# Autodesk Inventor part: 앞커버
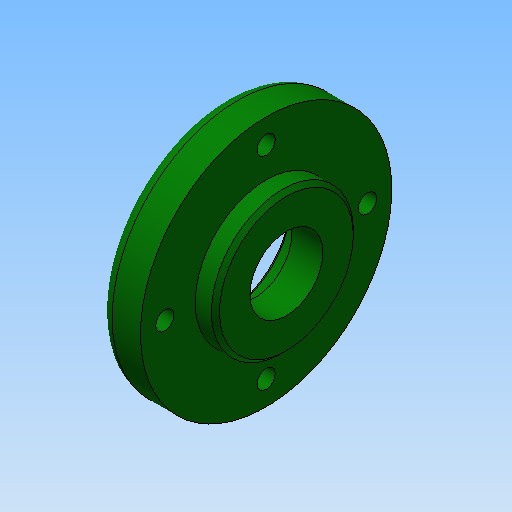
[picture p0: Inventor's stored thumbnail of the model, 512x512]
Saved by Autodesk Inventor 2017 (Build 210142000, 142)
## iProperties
Created: 2015-12
Part Number: 앞커버
Document SubType Name: Modeling
Designer: mdu
Density: 2.71 g/cm^3
Material: 알루미늄 6061
Mass: 70.9292 g
Surface Area: 93.9278 cm^2
Volume: 26.1731 cm^3
Appearance: 진녹색
Author: mdu
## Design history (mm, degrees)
sketch "스케치1"
  geometry: L1 (-7.5, 0)-(7.5, 0); L2 (-7.5, 0)-(-7.5, 31); L3 (-7.5, 31)-(2.5, 31); L4 (2.5, 31)-(2.5, 17.5); L5 (2.5, 17.5)-(7.5, 17.5); L6 (7.5, 17.5)-(7.5, 0); 2 further points
  constraints: 12 end point, 3 perpendicular, 1 coincident, 1 horizontal, 1 midpoint, 1 parallel
  dimensions: "d0" = 15 distance of L1.start L1.end; "d1" = 62 diameter of L3 L1; "d2" = 35 diameter of L5 L1; "d5" = 10 distance of L2.end L3.end
revolve "회전1" sketch "스케치1" stored, may be unused: angle "d6" = 90 deg
sketch "스케치2" dims "d42" = 50
  geometry: 3 further points
  constraints: 2 vertical alignment, 1 coincident, 2 other
hole "구멍1" sketch "스케치2" at (0, 25) diameter "d8" = 4.5; stored, may be unused: countersink angle "d12" = 90 deg, drill point angle "d14" = 118 deg; dims "d9" = 6, "d10" = 8, "d11" = 4.4, "d13" = 8
hole "구멍2" diameter "d20" = 18; stored, may be unused: countersink angle "d24" = 90 deg, drill point angle "d26" = 0 deg; dims "d18" = 10, "d19" = 10, "d21" = 6, "d22" = 8, "d23" = 4.4, "d25" = 8
hole "구멍3" diameter "d34" = 30; stored, may be unused: countersink angle "d38" = 90 deg, drill point angle "d40" = 0 deg; dims "d32" = 10, "d33" = 10, "d35" = 6, "d36" = 4, "d37" = 2, "d39" = 7.3
fillet "모깎기1" dims "d27" = 3, "d41" = 0.3
chamfer "모따기1" distance "d29" = 1; stored, may be unused: second distance "d30" = 2, angle "d31" = 45 deg
node "솔리드1"
pattern_circular "원형 패턴1" dims angle "d16" = 360 deg
